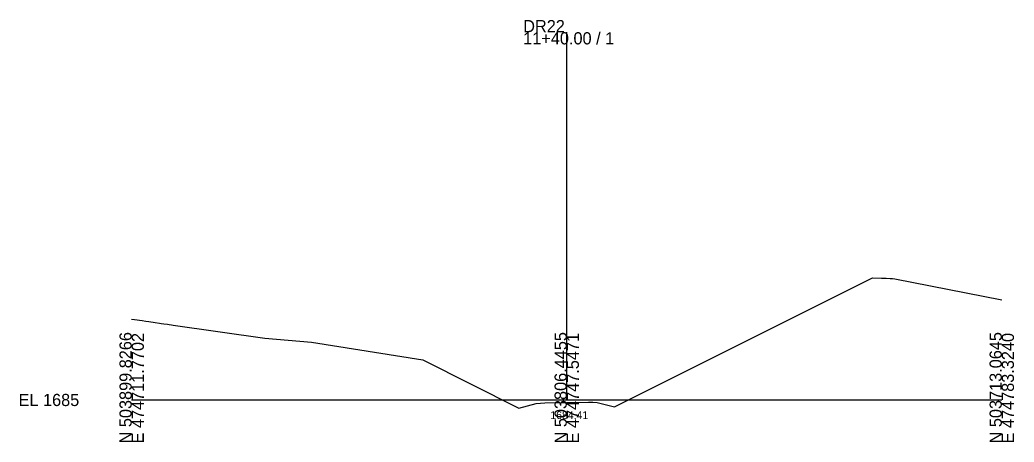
# Model space of a CAD drawing. Extents: x -26 to 1203, y -10 to 9633.
# Drawn here: x -25.7 to 202.8, y 3490.3 to 3587.4 of the extents above; entities that cross this region are included whole.
import ezdxf

# ---------------------------------------------------------------- set-up
doc = ezdxf.new("R2010")
doc.units = 0
for name, color, linetype in [('Exist Cross Section Cell', 7, 'Continuous'), ('Exist XS Center Line Elevation Label', 7, 'Continuous'), ('Exist XS Ground Line', 7, 'Continuous'), ('Scratch_Level_5', 7, 'Continuous')]:
    doc.layers.add(name, color=color, linetype=linetype)

msp = doc.modelspace()

# ---------------------------------------------------------------- linework, layer by layer
at = {"layer": 'Exist Cross Section Cell'}
for p, q in [((100, 3500), (100, 3584.54)), ((0, 3500), (100, 3500)), ((100, 3500), (200, 3500))]:
    msp.add_line(p, q, dxfattribs=at)
at = {"layer": 'Exist XS Ground Line'}
msp.add_lwpolyline([(0, 3518.56), (0.68, 3518.47), (2.38, 3518.23), (3.26, 3518.11), (3.97, 3518.01), (5.43, 3517.81), (6.43, 3517.67), (6.81, 3517.61), (7.4, 3517.53), (8.24, 3517.42), (8.6, 3517.37), (9.18, 3517.28), (9.56, 3517.23), (30.63, 3514.17), (41.31, 3513.27), (66.93, 3509.19), (89, 3498.15), (93, 3499.15), (93.98, 3499.23), (95, 3499.31), (100, 3499.41), (105, 3499.51), (106.02, 3499.47), (107, 3499.43), (111, 3498.43), (170.3, 3528.08), (172.34, 3528.02), (173.43, 3527.99), (174.33, 3527.96), (174.92, 3527.9), (175.45, 3527.82), (200, 3523.01)], dxfattribs=at)
at = {"layer": 'Scratch_Level_5'}
msp.add_lwpolyline([(0, 3518.56), (0.68, 3518.47), (2.38, 3518.23), (3.26, 3518.11), (3.97, 3518.01), (5.43, 3517.81), (6.43, 3517.67), (6.81, 3517.61), (7.4, 3517.53), (8.24, 3517.42), (8.6, 3517.37), (9.18, 3517.28), (9.56, 3517.23), (30.63, 3514.17), (41.31, 3513.27), (66.93, 3509.19), (89, 3498.15), (93, 3499.15), (93.98, 3499.23), (95, 3499.31), (100, 3499.41), (105, 3499.51), (106.02, 3499.47), (107, 3499.43), (111, 3498.43), (170.3, 3528.08), (172.34, 3528.02), (173.43, 3527.99), (174.33, 3527.96), (174.92, 3527.9), (175.45, 3527.82), (200, 3523.01)], dxfattribs=at)

# ---------------------------------------------------------------- texts
at = {"layer": 'Exist Cross Section Cell'}
for s, p in [('DR22', (90, 3584.54)), ('11+40.00 / 1', (90, 3581.74)), ('EL 1685', (-26, 3498.6))]:
    msp.add_text(s, height=2.8, dxfattribs=at).set_placement(p)
for s, p in [('N 503899.8266', (0, 3490)), ('E 474711.7702', (2.8, 3490)), ('N 503806.4455', (100, 3490)), ('E 474747.5471', (102.8, 3490)), ('N 503713.0645', (200, 3490)), ('E 474783.3240', (202.8, 3490))]:
    msp.add_text(s, height=2.8, rotation=90, dxfattribs=at).set_placement(p)
at = {"layer": 'Exist XS Center Line Elevation Label'}
msp.add_text('1684.41', height=1.8, dxfattribs=at).set_placement((96.24, 3495.61))

doc.saveas('drawing.dxf')
